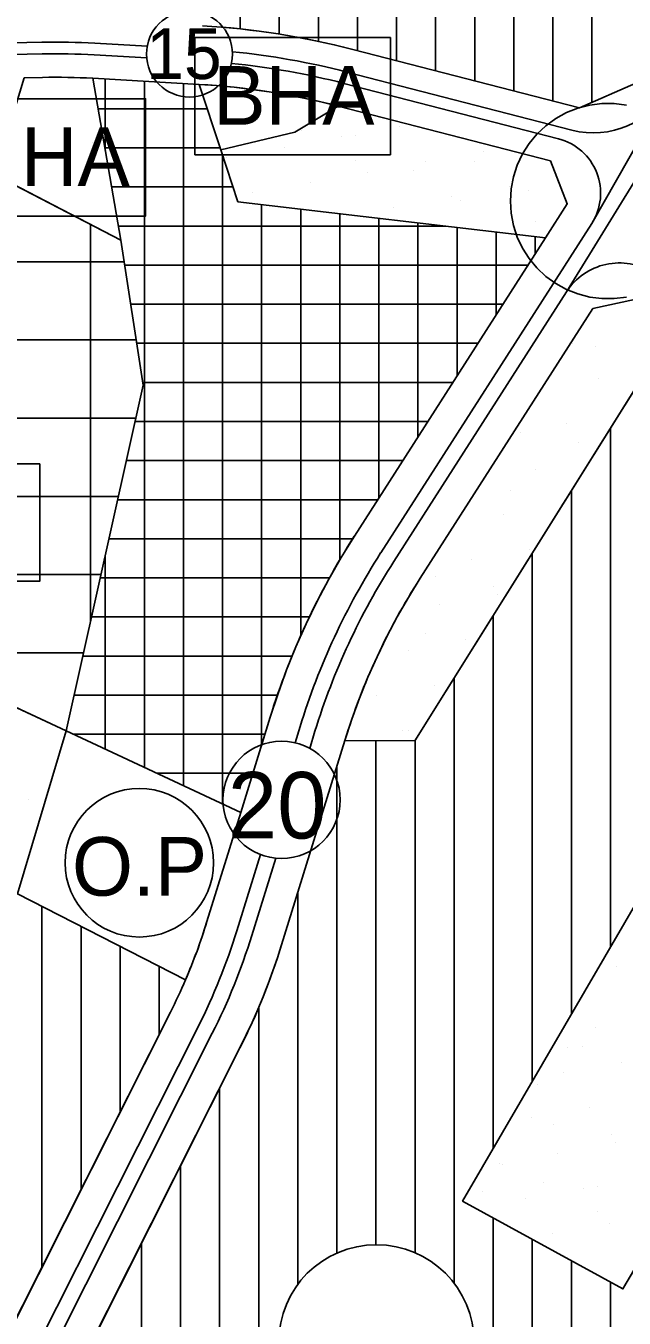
# Model space of a CAD drawing. Extents: x 419109 to 421295, y 4452223 to 4457798.
# Drawn here: x 419301.3 to 419454.4, y 4452731.2 to 4453061.8 of the extents above; entities that cross this region are included whole.
import ezdxf

# ---------------------------------------------------------------- set-up
doc = ezdxf.new("R2010")
doc.units = 0
for name, color, linetype in [('ADA', 7, 'Continuous'), ('ADAKENARI', 7, 'Continuous'), ('Default', 7, 'Continuous'), ('KALDIRIM', 7, 'Continuous'), ('KD_DAIRE', 7, 'Continuous'), ('KD_KAV_25', 7, 'Continuous'), ('KD_YGEN', 7, 'Continuous'), ('LJ_SEMBOL', 7, 'Continuous'), ('PL_AYA_PARK_DINLENME', 7, 'Continuous'), ('PL_K_BHA', 7, 'Continuous'), ('PL_K_PAZAR_ALANI', 7, 'Continuous'), ('PL_K_TALI_IS_MRK', 7, 'Continuous'), ('PL_KON_MEV_350', 7, 'Continuous'), ('PL_TA_K_OTOPARK', 7, 'Continuous'), ('SM_DAIRE', 7, 'Continuous'), ('TR_ORTAYOGUNKONUT', 7, 'Continuous'), ('TR_PARKALANI', 7, 'Continuous'), ('TR_PAZARLAMAAL', 7, 'Continuous'), ('TR_TALIISMERK', 7, 'Continuous'), ('TR_YONETIMMERK', 7, 'Continuous')]:
    doc.layers.add(name, color=color, linetype=linetype)

# ---------------------------------------------------------------- blocks, each defined once
blk = doc.blocks.new('POINT_DISPLAY')
at = {"layer": 'Default'}
blk.add_line((0, 0), (0, 0), dxfattribs=at)
blk = doc.blocks.new('OTOPARK_2')
at = {"layer": 'ADAKENARI'}
blk.add_circle((-299.724556, 162.1767), 190, dxfattribs=at)
blk.add_text('O.P', height=150, dxfattribs=at).set_placement((-472.039072, 77.96801))

msp = doc.modelspace()

# ---------------------------------------------------------------- linework, layer by layer
at = {"layer": 'ADA'}
for p, q in [((419325.56, 4453006.95), (419318.41, 4453048.33)), ((419345.58, 4453046.78), (419351.12, 4453030.04)), ((419381.16, 4453041.22), (419370.07, 4453034.55)), ((419370.07, 4453034.55), (419351.12, 4453030.04)), ((419351.12, 4453030.04), (419355.52, 4453016.76)), ((419293.32, 4453023.62), (419325.56, 4453006.95)), ((419355.52, 4453016.76), (419434.23, 4453007.55)), ((419331.27, 4452969.87), (419325.56, 4453006.95)), ((419468.52, 4452987.05), (419400.78, 4452878.87)), ((419311.59, 4452881.39), (419331.27, 4452969.87)), ((419257.84, 4452906.47), (419311.59, 4452881.39)), ((419299.09, 4452839.71), (419311.59, 4452881.39)), ((419311.59, 4452881.39), (419356.25, 4452860.54)), ((419400.78, 4452878.87), (419382.89, 4452878.97)), ((419299.09, 4452839.71), (419342.11, 4452817.7)), ((419459.65, 4452841.17), (419413.02, 4452761.13)), ((419454.03, 4452738.65), (419499.67, 4452816.04)), ((419413.02, 4452761.13), (419454.03, 4452738.65))]:
    msp.add_line(p, q, dxfattribs=at)
at = {"layer": 'ADAKENARI'}
for p, q in [((419442.9, 4453040.77), (419384.91, 4453055.74)), ((419300.84, 4453048.47), (419305.54, 4453048.57)), ((419318.41, 4453048.33), (419345.58, 4453046.78)), ((419457.35, 4453047.06), (419442.9, 4453040.77)), ((419381.16, 4453041.22), (419435.52, 4453027.18)), ((419435.52, 4453027.18), (419439.81, 4453016.26)), ((419439.81, 4453016.26), (419434.23, 4453007.55)), ((419434.23, 4453007.55), (419385.32, 4452931.22)), ((419446.37, 4452989.43), (419460.17, 4452992.43)), ((419402.16, 4452920.43), (419446.37, 4452989.43)), ((419363.79, 4452884.89), (419356.25, 4452860.54)), ((419366.72, 4452826.71), (419382.89, 4452878.97)), ((419356.25, 4452860.54), (419347.61, 4452832.62)), ((419338.26, 4452809.45), (419290.93, 4452715.56)), ((419310.85, 4452710.65), (419356.12, 4452800.45))]:
    msp.add_line(p, q, dxfattribs=at)
for centre, radius, start, end in [((419335.02, 4452862.53), 199.55, 75.5212, 86.7188), ((419308.97, 4452883.6), 165, 86.7188, 91.1911), ((419335.02, 4452862.53), 184.55, 75.5212, 86.7188), ((419545.29, 4452828.71), 190, 147.3481, 162.8036), ((419545.29, 4452828.71), 170, 147.3481, 162.8036), ((419204.32, 4452876.97), 150, 336.7264, 342.8036), ((419204.32, 4452876.97), 170, 333.2472, 342.8036), ((419204.32, 4452876.97), 150, 333.2472, 336.7264)]:
    msp.add_arc(centre, radius, start, end, dxfattribs=at)
at = {"layer": 'KALDIRIM'}
for p, q in [((419305.35, 4453057.57), (419284.15, 4453057.13)), ((419332.32, 4453056.55), (419318.93, 4453057.32)), ((419305.41, 4453054.57), (419284.22, 4453054.13)), ((419332.18, 4453053.55), (419318.75, 4453054.32)), ((419437.56, 4453032.85), (419382.66, 4453047.03)), ((419441.01, 4453035.06), (419383.41, 4453049.93)), ((419446.06, 4453011.19), (419465.79, 4453045.85)), ((419439.64, 4452993.75), (419460.26, 4453027.25)), ((419392.06, 4452926.91), (419446.06, 4453011.19)), ((419395.43, 4452924.75), (419439.64, 4452993.75)), ((419370.14, 4452878.36), (419371.43, 4452882.52)), ((419373.89, 4452876.93), (419375.25, 4452881.34)), ((419355.26, 4452830.26), (419361.3, 4452849.77)), ((419359.08, 4452829.08), (419365.19, 4452848.84)), ((419345.41, 4452805.85), (419295.97, 4452707.79)), ((419348.98, 4452804.05), (419303.75, 4452714.33))]:
    msp.add_line(p, q, dxfattribs=at)
for centre, radius, start, end in [((419308.97, 4452883.6), 174, 86.7188, 91.1911), ((419308.97, 4452883.6), 171, 86.7188, 91.1911), ((419335.02, 4452862.53), 193.55, 75.5212, 84.3363), ((419335.02, 4452862.53), 190.55, 75.5212, 84.3222), ((419446.49, 4453056.31), 21.95, 255.5212, 331.5469), ((419433.97, 4453018.94), 14.37, 327.3481, 75.5212), ((419453.09, 4452985.13), 15.97, 57.2023, 147.3481), ((419545.29, 4452828.71), 182, 147.3481, 162.8036), ((419545.29, 4452828.71), 178, 147.3481, 162.8036), ((419204.32, 4452876.97), 158, 333.2472, 342.8036), ((419204.32, 4452876.97), 162, 333.2472, 342.8036)]:
    msp.add_arc(centre, radius, start, end, dxfattribs=at)
at = {"layer": 'KD_DAIRE'}
for centre, radius in [((419343.13, 4453054.54), 11), ((419366.71, 4452863.76), 15)]:
    msp.add_circle(centre, radius, dxfattribs=at)
at = {"layer": 'KD_KAV_25'}
for p, q in [((419442.52, 4453040.71), (419439.6, 4453039.55)), ((419445.56, 4453041.49), (419442.52, 4453040.71)), ((419448.68, 4453041.88), (419445.56, 4453041.49)), ((419451.82, 4453041.88), (419448.68, 4453041.88)), ((419454.93, 4453041.49), (419451.82, 4453041.88)), ((419436.85, 4453038.04), (419434.31, 4453036.2)), ((419439.6, 4453039.55), (419436.85, 4453038.04)), ((419432.02, 4453034.05), (419430.02, 4453031.63)), ((419434.31, 4453036.2), (419432.02, 4453034.05)), ((419430.02, 4453031.63), (419428.34, 4453028.98)), ((419428.34, 4453028.98), (419427, 4453026.14)), ((419427, 4453026.14), (419426.03, 4453023.15)), ((419426.03, 4453023.15), (419425.44, 4453020.07)), ((419425.44, 4453020.07), (419425.25, 4453016.93)), ((419425.25, 4453016.93), (419425.44, 4453013.8)), ((419425.44, 4453013.8), (419426.03, 4453010.71)), ((419426.03, 4453010.71), (419427, 4453007.73)), ((419427, 4453007.73), (419428.34, 4453004.89)), ((419428.34, 4453004.89), (419430.02, 4453002.24)), ((419430.02, 4453002.24), (419432.02, 4452999.82)), ((419432.02, 4452999.82), (419434.31, 4452997.67)), ((419434.31, 4452997.67), (419436.85, 4452995.82)), ((419436.85, 4452995.82), (419439.6, 4452994.31)), ((419439.6, 4452994.31), (419442.52, 4452993.16)), ((419442.52, 4452993.16), (419445.56, 4452992.38)), ((419445.56, 4452992.38), (419448.68, 4452991.98)), ((419448.68, 4452991.98), (419451.82, 4452991.98)), ((419451.82, 4452991.98), (419454.93, 4452992.38))]:
    msp.add_line(p, q, dxfattribs=at)
at = {"layer": 'LJ_SEMBOL'}
msp.add_line((419344.53, 4453028.76), (419344.53, 4453028.76), dxfattribs=at)
for points in [[(419344.53, 4453058.76), (419394.53, 4453058.76), (419394.53, 4453028.76), (419344.53, 4453028.76), (419344.53, 4453058.76), (419394.53, 4453058.76)], [(419281.91, 4453043.1), (419331.91, 4453043.1), (419331.91, 4453013.1), (419281.91, 4453013.1), (419281.91, 4453043.1), (419331.91, 4453043.1)]]:
    msp.add_lwpolyline(points, dxfattribs=at)
msp.add_lwpolyline([(419274.81, 4452919.69), (419304.81, 4452919.69), (419304.81, 4452949.69), (419274.81, 4452949.69)], close=True, dxfattribs=at)
at = {"layer": 'PL_AYA_PARK_DINLENME'}
for points in [[(419435.52, 4453027.18), (419439.81, 4453016.26), (419434.23, 4453007.55), (419355.52, 4453016.76), (419351.12, 4453030.04), (419370.07, 4453034.55), (419381.16, 4453041.22)], [(419468.52, 4452987.05), (419400.78, 4452878.87), (419382.89, 4452878.97), (419384.68, 4452884.42), (419386.65, 4452889.8), (419388.8, 4452895.12), (419391.13, 4452900.35), (419393.63, 4452905.51), (419396.31, 4452910.58), (419399.15, 4452915.56), (419402.16, 4452920.43), (419446.37, 4452989.43), (419460.17, 4452992.43)], [(419231.01, 4452817.88), (419257.84, 4452906.47), (419311.59, 4452881.39), (419299.09, 4452839.71), (419270.63, 4452854.26), (419247.99, 4452809.79)], [(419459.65, 4452841.17), (419498.35, 4452820.34), (419499.67, 4452816.04), (419454.03, 4452738.65), (419413.02, 4452761.13)]]:
    msp.add_lwpolyline(points, close=True, dxfattribs=at)
at = {"layer": 'PL_K_BHA'}
for points in [[(419300.84, 4453048.47), (419305.54, 4453048.57), (419307.15, 4453048.59), (419308.76, 4453048.6), (419310.37, 4453048.6), (419311.98, 4453048.58), (419313.59, 4453048.54), (419315.19, 4453048.49), (419316.8, 4453048.42), (419318.41, 4453048.33), (419318.41, 4453048.33), (419325.56, 4453006.95), (419293.32, 4453023.62), (419296.65, 4453034.64)], [(419345.58, 4453046.78), (419350.08, 4453046.46), (419354.57, 4453046.04), (419359.04, 4453045.51), (419363.51, 4453044.87), (419367.95, 4453044.12), (419372.38, 4453043.26), (419376.78, 4453042.29), (419381.16, 4453041.22), (419370.07, 4453034.55), (419351.12, 4453030.04)]]:
    msp.add_lwpolyline(points, close=True, dxfattribs=at)
at = {"layer": 'PL_K_PAZAR_ALANI'}
msp.add_lwpolyline([(419257.84, 4452906.47), (419293.32, 4453023.62), (419325.56, 4453006.95), (419331.27, 4452969.87), (419311.59, 4452881.39)], close=True, dxfattribs=at)
at = {"layer": 'PL_K_TALI_IS_MRK'}
msp.add_lwpolyline([(419351.12, 4453030.04), (419355.52, 4453016.76), (419434.23, 4453007.55), (419385.32, 4452931.22), (419381.96, 4452925.77), (419378.78, 4452920.21), (419375.79, 4452914.55), (419372.99, 4452908.78), (419370.39, 4452902.93), (419367.99, 4452896.99), (419365.79, 4452890.97), (419363.79, 4452884.89), (419356.25, 4452860.54), (419311.59, 4452881.39), (419331.27, 4452969.87), (419325.56, 4453006.95), (419318.41, 4453048.33), (419318.41, 4453048.33), (419345.58, 4453046.78)], close=True, dxfattribs=at)
at = {"layer": 'PL_KON_MEV_350'}
for points in [[(419521.56, 4453165.57), (419457.35, 4453047.06), (419442.9, 4453040.77), (419384.91, 4453055.74), (419380.18, 4453056.9), (419375.41, 4453057.95), (419370.63, 4453058.88), (419365.82, 4453059.69), (419361, 4453060.38), (419356.16, 4453060.96), (419351.3, 4453061.41), (419346.44, 4453061.75)], [(419310.85, 4452710.65), (419356.12, 4452800.45), (419357.68, 4452803.63), (419359.18, 4452806.84), (419360.61, 4452810.09), (419361.97, 4452813.36), (419363.26, 4452816.66), (419364.48, 4452819.99), (419365.64, 4452823.34), (419366.72, 4452826.71), (419382.89, 4452878.97), (419400.78, 4452878.87), (419468.52, 4452987.05)], [(419299.09, 4452839.71), (419342.11, 4452817.7), (419341.66, 4452816.66), (419341.2, 4452815.62), (419340.73, 4452814.58), (419340.25, 4452813.55), (419339.77, 4452812.52), (419339.27, 4452811.49), (419338.77, 4452810.47), (419338.26, 4452809.45), (419290.93, 4452715.56)], [(419459.65, 4452841.17), (419413.02, 4452761.13), (419454.03, 4452738.65), (419499.67, 4452816.04)]]:
    msp.add_lwpolyline(points, dxfattribs=at)
at = {"layer": 'PL_TA_K_OTOPARK'}
msp.add_lwpolyline([(419356.25, 4452860.54), (419347.61, 4452832.62), (419347.01, 4452830.73), (419346.39, 4452828.84), (419345.74, 4452826.96), (419345.06, 4452825.09), (419344.36, 4452823.23), (419343.64, 4452821.38), (419342.89, 4452819.54), (419342.11, 4452817.7), (419299.09, 4452839.71), (419311.59, 4452881.39)], close=True, dxfattribs=at)
at = {"layer": 'SM_DAIRE'}
msp.add_circle((419390.96, 4452724.96), 25, dxfattribs=at)
at = {"layer": 'TR_ORTAYOGUNKONUT'}
for p, q in [((419396.12, 4453052.85), (419396.12, 4453195.63)), ((419406.12, 4453050.26), (419406.12, 4453193.99)), ((419416.12, 4453047.68), (419416.12, 4453192.36)), ((419426.12, 4453045.1), (419426.12, 4453190.73)), ((419436.12, 4453042.52), (419436.12, 4453189.09)), ((419446.12, 4453042.17), (419446.12, 4453187.46)), ((419386.12, 4453055.43), (419386.12, 4453104.91)), ((419356.12, 4453060.96), (419356.12, 4453099.18)), ((419366.12, 4453059.64), (419366.12, 4453096.52)), ((419376.12, 4453057.79), (419376.12, 4453098.06)), ((419450.85, 4452826.07), (419450.85, 4452958.84)), ((419440.85, 4452808.9), (419440.85, 4452942.87)), ((419430.85, 4452791.74), (419430.85, 4452926.9)), ((419420.85, 4452774.58), (419420.85, 4452910.93)), ((419410.85, 4452740.1), (419410.85, 4452894.96)), ((419390.85, 4452749.96), (419390.85, 4452878.93)), ((419400.85, 4452747.92), (419400.85, 4452878.99)), ((419380.85, 4452747.83), (419380.85, 4452872.38)), ((419370.85, 4452739.82), (419370.85, 4452840.07)), ((419305.39, 4452744.24), (419305.39, 4452836.48)), ((419315.39, 4452764.08), (419315.39, 4452831.37)), ((419325.39, 4452783.91), (419325.39, 4452826.25)), ((419335.39, 4452803.75), (419335.39, 4452821.14)), ((419360.85, 4452666.37), (419360.85, 4452810.68)), ((419350.85, 4452672.86), (419350.85, 4452790)), ((419340.85, 4452679.34), (419340.85, 4452770.16)), ((419420.85, 4452627.45), (419420.85, 4452756.84)), ((419330.85, 4452685.83), (419330.85, 4452750.32)), ((419430.85, 4452620.97), (419430.85, 4452751.36)), ((419440.85, 4452615.25), (419440.85, 4452745.87)), ((419450.85, 4452610.9), (419450.85, 4452740.39))]:
    msp.add_line(p, q, dxfattribs=at)
at = {"layer": 'TR_PAZARLAMAAL'}
for p, q in [((419317.84, 4452909.49), (419317.84, 4453010.94)), ((419286.58, 4453001.39), (419326.42, 4453001.39)), ((419280.53, 4452981.39), (419329.49, 4452981.39)), ((419274.47, 4452961.39), (419329.38, 4452961.39)), ((419268.41, 4452941.39), (419324.93, 4452941.39)), ((419262.36, 4452921.39), (419320.49, 4452921.39)), ((419268.74, 4452901.39), (419316.04, 4452901.39))]:
    msp.add_line(p, q, dxfattribs=at)
at = {"layer": 'TR_TALIISMERK'}
for p, q in [((419321.59, 4453029.9), (419321.59, 4453048.15)), ((419331.59, 4452872.05), (419331.59, 4453047.58)), ((419341.59, 4452867.39), (419341.59, 4453047)), ((419319.75, 4453040.54), (419347.64, 4453040.54)), ((419321.48, 4453030.54), (419350.96, 4453030.54)), ((419351.59, 4452862.72), (419351.59, 4453028.62)), ((419323.21, 4453020.54), (419354.27, 4453020.54)), ((419361.59, 4452877.79), (419361.59, 4453016.05)), ((419371.59, 4452905.64), (419371.59, 4453014.88)), ((419324.94, 4453010.54), (419408.67, 4453010.54)), ((419381.59, 4452925.14), (419381.59, 4453013.71)), ((419391.59, 4452941.01), (419391.59, 4453012.54)), ((419401.59, 4452956.62), (419401.59, 4453011.37)), ((419411.59, 4452972.22), (419411.59, 4453010.2)), ((419421.59, 4452987.83), (419421.59, 4453009.03)), ((419431.59, 4453003.43), (419431.59, 4453007.86)), ((419326.55, 4453000.54), (419429.74, 4453000.54)), ((419328.08, 4452990.54), (419423.33, 4452990.54)), ((419329.62, 4452980.54), (419416.93, 4452980.54)), ((419331.16, 4452970.54), (419410.52, 4452970.54)), ((419329.19, 4452960.54), (419404.11, 4452960.54)), ((419326.97, 4452950.54), (419397.7, 4452950.54)), ((419324.74, 4452940.54), (419391.29, 4452940.54)), ((419322.52, 4452930.54), (419384.9, 4452930.54)), ((419321.59, 4452876.72), (419321.59, 4452926.36)), ((419320.3, 4452920.54), (419378.97, 4452920.54)), ((419318.07, 4452910.54), (419373.85, 4452910.54)), ((419315.85, 4452900.54), (419369.42, 4452900.54)), ((419313.63, 4452890.54), (419365.64, 4452890.54)), ((419313.4, 4452880.54), (419362.44, 4452880.54)), ((419334.83, 4452870.54), (419359.35, 4452870.54))]:
    msp.add_line(p, q, dxfattribs=at)

# ---------------------------------------------------------------- block references
at = {"layer": 'LJ_SEMBOL', "xscale": 0.1, "yscale": 0.10000000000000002}
msp.add_blockref('OTOPARK_2', (419360.28, 4452831.45), dxfattribs=at)
at = {"layer": 'TR_PARKALANI', "xscale": 0.1, "yscale": 0.10000000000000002}
for p in [(419371.76, 4453034.87), (419385.67, 4453033.75), (419396.89, 4453035.93), (419367.35, 4453030.72), (419382.12, 4453033.33), (419352.57, 4453028.12), (419385.67, 4453027.34), (419416.08, 4453027.06), (419418.32, 4453029.56), (419388.78, 4453024.35), (419400.44, 4453024.74), (419403.55, 4453026.95), (419374.01, 4453021.74), (419424.98, 4453020.58), (419359.24, 4453019.14), (419410.21, 4453017.97), (419412.61, 4453017.19), (419429.98, 4453019.53), (419395.44, 4453015.37), (419431.64, 4453011.6), (419441.13, 4452980.53), (419446.97, 4452979.77), (419447.79, 4452971.55), (419427.86, 4452957.75), (419439.68, 4452959.97), (419442.63, 4452955.15), (419431.56, 4452948.38), (419425.25, 4452942.98), (419438.22, 4452939.4), (419423.45, 4452936.8), (419415.34, 4452925.21), (419430.11, 4452927.82), (419406.14, 4452920.97), (419420.91, 4452918.36), (419422, 4452916.23), (419407.23, 4452913.63), (419403.53, 4452906.19), (419399.12, 4452902.04), (419413.89, 4452904.65), (419405.78, 4452893.06), (419391.01, 4452890.46), (419399.19, 4452881.57), (419397.67, 4452881.48), (419302.05, 4452863.76), (419452.5, 4452821.19), (419446.92, 4452805.55), (419439.74, 4452800.43), (419443.61, 4452800.68), (419453.58, 4452796.57), (419438.81, 4452793.96), (419432.11, 4452791.04), (419445.47, 4452784.98), (419430.7, 4452782.38), (419436.27, 4452780.74), (419451.04, 4452778.13), (419452.13, 4452776), (419437.36, 4452773.4), (419422.58, 4452770.79), (419423.22, 4452770.52), (419433.66, 4452765.96), (419418.02, 4452763.65), (419444.02, 4452764.42), (419447.57, 4452764.84), (419429.24, 4452761.81), (419447.57, 4452758.44), (419435.91, 4452752.83), (419450.68, 4452755.44), (419444.96, 4452743.66)]:
    msp.add_blockref('POINT_DISPLAY', p, dxfattribs=at)
at = {"layer": 'TR_YONETIMMERK', "xscale": 0.1, "yscale": 0.10000000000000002}
msp.add_blockref('POINT_DISPLAY', (419318.32, 4453031.95), dxfattribs=at)

# ---------------------------------------------------------------- texts
at = {"layer": 'KD_YGEN'}
for s, height, p in [('15', 13, (419332.04, 4453048.15)), ('20', 17, (419352.94, 4452853.87))]:
    msp.add_text(s, height=height, dxfattribs=at).set_placement(p)
at = {"layer": 'LJ_SEMBOL'}
for p in [(419349.23, 4453036.45), (419286.61, 4453020.79)]:
    msp.add_text('BHA', height=15, dxfattribs=at).set_placement(p)

doc.saveas('drawing.dxf')
